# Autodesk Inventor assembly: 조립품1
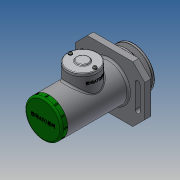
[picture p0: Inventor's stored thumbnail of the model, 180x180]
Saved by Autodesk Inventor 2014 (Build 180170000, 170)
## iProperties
Created: 2017-10
Part Number: 조립품1
Document SubType Name: Assembly
Designer: NET
Author: NET
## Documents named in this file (20)
- C:\Users\NET\Desktop\471007V1030\조립품1.iam
- C:\Users\NET\Desktop\471007V1030\본체.ipt
- C:\Users\NET\Desktop\471007V1030\V-벨트풀리.ipt
- C:\Users\NET\Desktop\471007V1030\너트 M10.ipt
- C:\Users\NET\Desktop\471007V1030\멈춤링 15 x 1.ipt
- C:\Users\NET\Desktop\471007V1030\멈춤링 35x1.6.ipt
- C:\Users\NET\Desktop\471007V1030\베어링 15 x 35 x 11.ipt
- C:\Users\NET\Desktop\471007V1030\볼트 M4 x 10.ipt
- C:\Users\NET\Desktop\471007V1030\부시1.ipt
- C:\Users\NET\Desktop\471007V1030\부시2.ipt
- C:\Users\NET\Desktop\471007V1030\사이드 커버.ipt
- 사이드 커버.ipt
- C:\Users\NET\Desktop\471007V1030\십자볼트 M3 x 10.ipt
- C:\Users\NET\Desktop\471007V1030\오일 실 15 25 7.ipt
- C:\Users\NET\Desktop\471007V1030\와셔 3x6.ipt
- C:\Users\NET\Desktop\471007V1030\와셔 4x16.ipt
- C:\Users\NET\Desktop\471007V1030\와셔 10x21.ipt
- C:\Users\NET\Desktop\471007V1030\축.ipt
- C:\Users\NET\Desktop\471007V1030\키 4 x 4 x 18.ipt
- C:\Users\NET\Desktop\471007V1030\탑 커버.ipt
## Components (2 placed, 2 different names)
1. V-벨트풀리:1
2. ISO 4017 M4 x 10:1
